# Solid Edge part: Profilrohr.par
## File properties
Dokumentum tartalom típus: 0
Last saved by: ahadarics
Revision: 76
Sűrűség: 0,000 kg/m^3
Pontosság: 0,990
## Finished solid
Body 1: solid body, 91 faces, 266 edges, 176 vertices.
  Faces by surface: plane 46, cylinder 45
  Edges by curve: line 176, circle 90
Bounding box of the edges (mm): 54.500 x 54.500 x 21.000, from (-27.25, -27.25, 0) to (27.25, 27.25, 21).
Cylindrical faces by radius (mm): R0.15 x20, R0.25 x20, R6.75 x4, R20 x1
Planar faces by outward normal: +x 11, +y 11, +z 1, -x 11, -y 11, -z 1
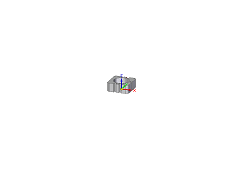
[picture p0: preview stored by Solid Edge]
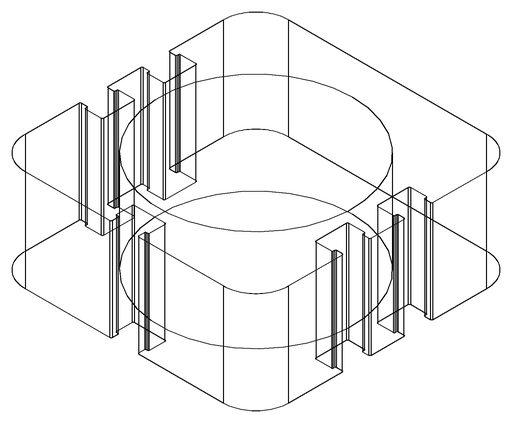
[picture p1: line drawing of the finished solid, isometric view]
